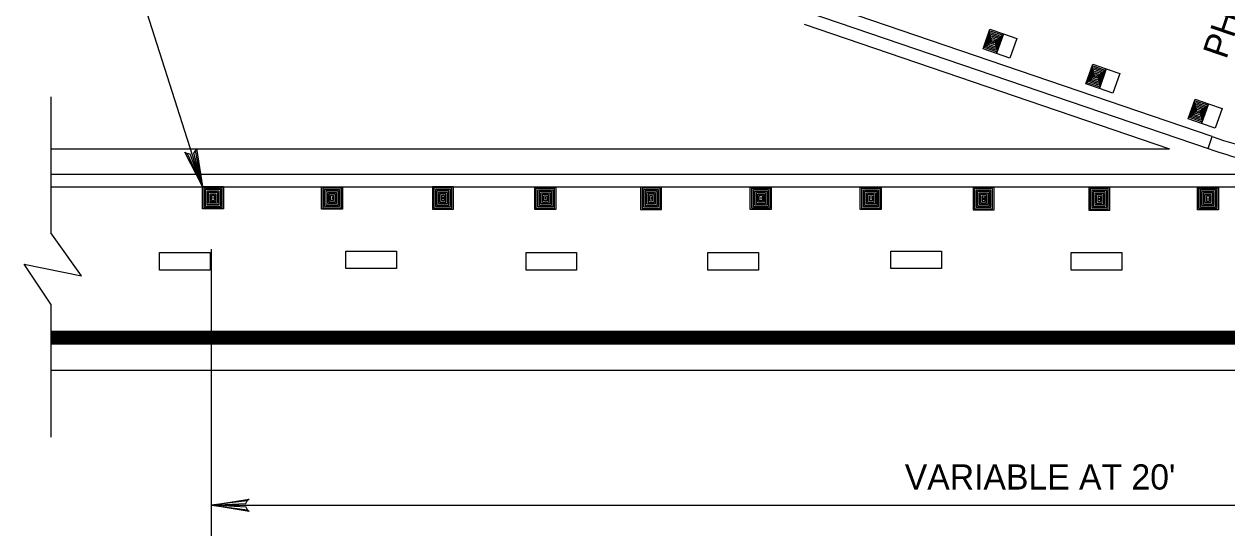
# Model space of a CAD drawing. Extents: x 639362 to 641108, y 298458 to 299646.
# Drawn here: x 639509.1 to 639652.3, y 299494 to 299554.9 of the extents above; entities that cross this region are included whole.
import ezdxf

# ---------------------------------------------------------------- set-up
doc = ezdxf.new("R2010")
doc.units = 0
doc.layers.add('2', color=7, linetype='Continuous')

msp = doc.modelspace()

# ---------------------------------------------------------------- linework, layer by layer
at = {"layer": '2'}
for p, q in [((639530.34, 299535.6), (639521.36, 299563.76)), ((639650.51, 299541.55), (639602.91, 299557.79)), ((639602.39, 299556.38), (639650.01, 299540.13)), ((639601.94, 299554.95), (639645.41, 299540.11)), ((639623.23, 299551.99), (639624.05, 299554.35)), ((639623.37, 299552.14), (639624.07, 299554.15)), ((639623.54, 299552.27), (639624.12, 299553.95)), ((639623.7, 299552.4), (639624.17, 299553.74)), ((639623.87, 299552.53), (639624.22, 299553.54)), ((639624.03, 299552.66), (639624.27, 299553.33)), ((639624.05, 299554.35), (639625.65, 299553.8)), ((639624.07, 299554.15), (639625.52, 299553.65)), ((639624.12, 299553.95), (639625.35, 299553.52)), ((639624.17, 299553.74), (639625.19, 299553.39)), ((639624.22, 299553.54), (639625.02, 299553.26)), ((639624.27, 299553.33), (639624.85, 299553.13)), ((639625.02, 299553.26), (639624.67, 299552.25)), ((639625.19, 299553.39), (639624.72, 299552.05)), ((639625.35, 299553.52), (639624.77, 299551.84)), ((639625.52, 299553.65), (639624.82, 299551.64)), ((639625.65, 299553.8), (639624.83, 299551.43)), ((639624.83, 299551.43), (639623.23, 299551.99)), ((639624.82, 299551.64), (639623.37, 299552.14)), ((639624.77, 299551.84), (639623.54, 299552.27)), ((639624.72, 299552.05), (639623.7, 299552.4)), ((639624.67, 299552.25), (639623.87, 299552.53)), ((639624.62, 299552.46), (639624.03, 299552.66)), ((639624.2, 299552.79), (639624.31, 299553.13)), ((639624.57, 299552.66), (639624.2, 299552.79)), ((639624.31, 299553.13), (639624.69, 299553)), ((639624.36, 299552.92), (639624.52, 299552.86)), ((639624.69, 299553), (639624.57, 299552.66)), ((639624.85, 299553.13), (639624.62, 299552.46)), ((639635.47, 299547.82), (639636.29, 299550.18)), ((639635.61, 299547.96), (639636.31, 299549.98)), ((639635.78, 299548.1), (639636.36, 299549.77)), ((639635.95, 299548.23), (639636.41, 299549.57)), ((639636.11, 299548.36), (639636.46, 299549.36)), ((639636.28, 299548.49), (639636.51, 299549.16)), ((639636.29, 299550.18), (639637.9, 299549.62)), ((639636.31, 299549.98), (639637.76, 299549.47)), ((639636.36, 299549.77), (639637.6, 299549.35)), ((639636.41, 299549.57), (639637.43, 299549.21)), ((639636.44, 299548.62), (639636.56, 299548.95)), ((639636.46, 299549.36), (639637.26, 299549.09)), ((639636.51, 299549.16), (639637.1, 299548.95)), ((639636.56, 299548.95), (639636.93, 299548.82)), ((639637.1, 299548.95), (639636.87, 299548.28)), ((639637.26, 299549.09), (639636.92, 299548.08)), ((639637.43, 299549.21), (639636.96, 299547.87)), ((639637.6, 299549.35), (639637.01, 299547.67)), ((639637.76, 299549.47), (639637.06, 299547.46)), ((639637.9, 299549.62), (639637.08, 299547.26)), ((639637.08, 299547.26), (639635.47, 299547.82)), ((639637.06, 299547.46), (639635.61, 299547.96)), ((639637.01, 299547.67), (639635.78, 299548.1)), ((639636.96, 299547.87), (639635.95, 299548.23)), ((639636.92, 299548.08), (639636.11, 299548.36)), ((639636.87, 299548.28), (639636.28, 299548.49)), ((639636.82, 299548.49), (639636.44, 299548.62)), ((639636.61, 299548.75), (639636.77, 299548.69)), ((639636.93, 299548.82), (639636.82, 299548.49)), ((639512.29, 299546.29), (639512.29, 299530.08)), ((639647.65, 299543.66), (639648.47, 299546.02)), ((639647.79, 299543.81), (639648.49, 299545.82)), ((639647.96, 299543.94), (639648.54, 299545.62)), ((639648.12, 299544.07), (639648.59, 299545.41)), ((639648.29, 299544.2), (639648.64, 299545.21)), ((639648.45, 299544.33), (639648.68, 299545)), ((639648.47, 299546.02), (639650.07, 299545.47)), ((639648.49, 299545.82), (639649.94, 299545.32)), ((639648.54, 299545.62), (639649.77, 299545.19)), ((639648.59, 299545.41), (639649.61, 299545.06)), ((639648.62, 299544.46), (639648.73, 299544.8)), ((639648.64, 299545.21), (639649.44, 299544.93)), ((639648.68, 299545), (639649.27, 299544.8)), ((639648.73, 299544.8), (639649.11, 299544.67)), ((639649.11, 299544.67), (639648.99, 299544.33)), ((639649.27, 299544.8), (639649.04, 299544.13)), ((639649.44, 299544.93), (639649.09, 299543.92)), ((639649.61, 299545.06), (639649.14, 299543.72)), ((639649.77, 299545.19), (639649.19, 299543.51)), ((639649.94, 299545.32), (639649.24, 299543.31)), ((639650.07, 299545.47), (639649.25, 299543.1)), ((639649.25, 299543.1), (639647.65, 299543.66)), ((639649.24, 299543.31), (639647.79, 299543.81)), ((639649.19, 299543.51), (639647.96, 299543.94)), ((639649.14, 299543.72), (639648.12, 299544.07)), ((639649.09, 299543.92), (639648.29, 299544.2)), ((639649.04, 299544.13), (639648.45, 299544.33)), ((639648.99, 299544.33), (639648.62, 299544.46)), ((639648.78, 299544.59), (639648.94, 299544.53)), ((639650.01, 299540.13), (639650.51, 299541.55)), ((639512.29, 299540.11), (639645.41, 299540.11)), ((639512.29, 299537.09), (639661.38, 299537.09)), ((639512.29, 299535.59), (639737.89, 299535.59)), ((639530.34, 299535.6), (639532.84, 299535.6)), ((639530.34, 299532.95), (639530.34, 299535.6)), ((639530.53, 299535.47), (639532.65, 299535.47)), ((639530.53, 299533.08), (639530.53, 299535.47)), ((639530.7, 299535.29), (639532.48, 299535.29)), ((639530.7, 299533.25), (639530.7, 299535.29)), ((639530.88, 299535.11), (639532.3, 299535.11)), ((639530.88, 299533.43), (639530.88, 299535.11)), ((639531.06, 299534.94), (639532.12, 299534.94)), ((639531.06, 299533.61), (639531.06, 299534.94)), ((639531.24, 299533.79), (639531.24, 299534.76)), ((639531.24, 299534.76), (639531.95, 299534.76)), ((639531.95, 299534.76), (639531.95, 299533.79)), ((639532.12, 299534.94), (639532.12, 299533.61)), ((639532.3, 299535.11), (639532.3, 299533.43)), ((639532.48, 299535.29), (639532.48, 299533.25)), ((639532.65, 299535.47), (639532.65, 299533.08)), ((639532.84, 299535.6), (639532.84, 299532.95)), ((639544.52, 299535.57), (639547.01, 299535.57)), ((639544.52, 299532.92), (639544.52, 299535.57)), ((639544.7, 299535.44), (639546.83, 299535.44)), ((639544.7, 299533.05), (639544.7, 299535.44)), ((639544.88, 299535.26), (639546.66, 299535.26)), ((639544.88, 299533.22), (639544.88, 299535.26)), ((639545.06, 299535.08), (639546.48, 299535.08)), ((639545.06, 299533.4), (639545.06, 299535.08)), ((639545.24, 299534.91), (639546.3, 299534.91)), ((639545.24, 299533.58), (639545.24, 299534.91)), ((639545.41, 299533.76), (639545.41, 299534.73)), ((639545.41, 299534.73), (639546.12, 299534.73)), ((639546.12, 299534.73), (639546.12, 299533.76)), ((639546.3, 299534.91), (639546.3, 299533.58)), ((639546.48, 299535.08), (639546.48, 299533.4)), ((639546.66, 299535.26), (639546.66, 299533.22)), ((639546.83, 299535.44), (639546.83, 299533.05)), ((639547.01, 299535.57), (639547.01, 299532.92)), ((639560.21, 299535.57), (639557.71, 299535.57)), ((639557.71, 299535.57), (639557.71, 299532.92)), ((639560.02, 299535.44), (639557.89, 299535.44)), ((639557.89, 299535.44), (639557.89, 299533.05)), ((639559.84, 299535.26), (639558.07, 299535.26)), ((639558.07, 299535.26), (639558.07, 299533.22)), ((639559.67, 299535.08), (639558.25, 299535.08)), ((639558.25, 299535.08), (639558.25, 299533.4)), ((639559.49, 299534.91), (639558.43, 299534.91)), ((639558.43, 299534.91), (639558.43, 299533.58)), ((639558.6, 299534.73), (639558.6, 299533.76)), ((639559.31, 299534.73), (639558.6, 299534.73)), ((639559.31, 299533.76), (639559.31, 299534.73)), ((639559.49, 299533.58), (639559.49, 299534.91)), ((639559.67, 299533.4), (639559.67, 299535.08)), ((639559.84, 299533.22), (639559.84, 299535.26)), ((639560.02, 299533.05), (639560.02, 299535.44)), ((639560.21, 299532.92), (639560.21, 299535.57)), ((639569.89, 299535.54), (639572.39, 299535.54)), ((639569.89, 299532.89), (639569.89, 299535.54)), ((639570.07, 299535.41), (639572.2, 299535.41)), ((639570.07, 299533.01), (639570.07, 299535.41)), ((639570.25, 299535.23), (639572.03, 299535.23)), ((639570.25, 299533.19), (639570.25, 299535.23)), ((639570.43, 299535.05), (639571.85, 299535.05)), ((639570.43, 299533.37), (639570.43, 299535.05)), ((639570.61, 299534.87), (639571.67, 299534.87)), ((639570.61, 299533.55), (639570.61, 299534.87)), ((639570.79, 299533.72), (639570.79, 299534.7)), ((639570.79, 299534.7), (639571.49, 299534.7)), ((639571.49, 299534.7), (639571.49, 299533.72)), ((639571.67, 299534.87), (639571.67, 299533.55)), ((639571.85, 299535.05), (639571.85, 299533.37)), ((639572.03, 299535.23), (639572.03, 299533.19)), ((639572.2, 299535.41), (639572.2, 299533.01)), ((639572.39, 299535.54), (639572.39, 299532.89)), ((639584.98, 299535.53), (639582.48, 299535.53)), ((639582.48, 299535.53), (639582.48, 299532.88)), ((639584.8, 299535.4), (639582.67, 299535.4)), ((639582.67, 299535.4), (639582.67, 299533)), ((639584.62, 299535.22), (639582.84, 299535.22)), ((639582.84, 299535.22), (639582.84, 299533.18)), ((639584.44, 299535.04), (639583.02, 299535.04)), ((639583.02, 299535.04), (639583.02, 299533.36)), ((639584.26, 299534.86), (639583.2, 299534.86)), ((639583.2, 299534.86), (639583.2, 299533.54)), ((639583.38, 299534.69), (639583.38, 299533.71)), ((639584.09, 299534.69), (639583.38, 299534.69)), ((639584.09, 299533.71), (639584.09, 299534.69)), ((639584.26, 299533.54), (639584.26, 299534.86)), ((639584.44, 299533.36), (639584.44, 299535.04)), ((639584.62, 299533.18), (639584.62, 299535.22)), ((639584.8, 299533), (639584.8, 299535.4)), ((639584.98, 299532.88), (639584.98, 299535.53)), ((639595.54, 299535.55), (639598.03, 299535.55)), ((639595.54, 299532.89), (639595.54, 299535.55)), ((639595.72, 299535.41), (639597.85, 299535.41)), ((639595.72, 299533.02), (639595.72, 299535.41)), ((639595.9, 299535.24), (639597.68, 299535.24)), ((639595.9, 299533.2), (639595.9, 299535.24)), ((639596.08, 299535.06), (639597.5, 299535.06)), ((639596.08, 299533.38), (639596.08, 299535.06)), ((639596.26, 299534.88), (639597.32, 299534.88)), ((639596.26, 299533.55), (639596.26, 299534.88)), ((639596.44, 299533.73), (639596.44, 299534.71)), ((639596.44, 299534.71), (639597.14, 299534.71)), ((639597.14, 299534.71), (639597.14, 299533.73)), ((639597.32, 299534.88), (639597.32, 299533.55)), ((639597.5, 299535.06), (639597.5, 299533.38)), ((639597.68, 299535.24), (639597.68, 299533.2)), ((639597.85, 299535.41), (639597.85, 299533.02)), ((639598.03, 299535.55), (639598.03, 299532.89)), ((639608.63, 299535.53), (639611.13, 299535.53)), ((639608.63, 299532.88), (639608.63, 299535.53)), ((639608.82, 299535.4), (639610.95, 299535.4)), ((639608.82, 299533.01), (639608.82, 299535.4)), ((639609, 299535.22), (639610.77, 299535.22)), ((639609, 299533.19), (639609, 299535.22)), ((639609.17, 299535.05), (639610.59, 299535.05)), ((639609.17, 299533.36), (639609.17, 299535.05)), ((639609.35, 299534.87), (639610.42, 299534.87)), ((639609.35, 299533.54), (639609.35, 299534.87)), ((639609.53, 299533.72), (639609.53, 299534.69)), ((639609.53, 299534.69), (639610.24, 299534.69)), ((639610.24, 299534.69), (639610.24, 299533.72)), ((639610.42, 299534.87), (639610.42, 299533.54)), ((639610.59, 299535.05), (639610.59, 299533.36)), ((639610.77, 299535.22), (639610.77, 299533.19)), ((639610.95, 299535.4), (639610.95, 299533.01)), ((639611.13, 299535.53), (639611.13, 299532.88)), ((639624.55, 299535.5), (639622.05, 299535.5)), ((639622.05, 299535.5), (639622.05, 299532.84)), ((639624.36, 299535.36), (639622.23, 299535.36)), ((639622.23, 299535.36), (639622.23, 299532.97)), ((639624.18, 299535.19), (639622.41, 299535.19)), ((639622.41, 299535.19), (639622.41, 299533.15)), ((639624.01, 299535.01), (639622.59, 299535.01)), ((639622.59, 299535.01), (639622.59, 299533.32)), ((639623.83, 299534.83), (639622.76, 299534.83)), ((639622.76, 299534.83), (639622.76, 299533.5)), ((639622.94, 299534.65), (639622.94, 299533.68)), ((639623.65, 299534.65), (639622.94, 299534.65)), ((639623.65, 299533.68), (639623.65, 299534.65)), ((639623.83, 299533.5), (639623.83, 299534.83)), ((639624.01, 299533.32), (639624.01, 299535.01)), ((639624.18, 299533.15), (639624.18, 299535.19)), ((639624.36, 299532.97), (639624.36, 299535.36)), ((639624.55, 299532.84), (639624.55, 299535.5)), ((639638.31, 299535.45), (639635.82, 299535.45)), ((639635.82, 299535.45), (639635.82, 299532.8)), ((639638.13, 299535.32), (639636, 299535.32)), ((639636, 299535.32), (639636, 299532.93)), ((639637.95, 299535.14), (639636.17, 299535.14)), ((639636.17, 299535.14), (639636.17, 299533.11)), ((639637.77, 299534.97), (639636.35, 299534.97)), ((639636.35, 299534.97), (639636.35, 299533.28)), ((639637.6, 299534.79), (639636.53, 299534.79)), ((639636.53, 299534.79), (639636.53, 299533.46)), ((639636.71, 299534.61), (639636.71, 299533.64)), ((639637.42, 299534.61), (639636.71, 299534.61)), ((639637.42, 299533.64), (639637.42, 299534.61)), ((639637.6, 299533.46), (639637.6, 299534.79)), ((639637.77, 299533.28), (639637.77, 299534.97)), ((639637.95, 299533.11), (639637.95, 299535.14)), ((639638.13, 299532.93), (639638.13, 299535.32)), ((639638.31, 299532.8), (639638.31, 299535.45)), ((639648.74, 299535.51), (639651.24, 299535.51)), ((639648.74, 299532.85), (639648.74, 299535.51)), ((639648.93, 299535.37), (639651.06, 299535.37)), ((639648.93, 299532.98), (639648.93, 299535.37)), ((639649.11, 299535.2), (639650.88, 299535.2)), ((639649.11, 299533.16), (639649.11, 299535.2)), ((639649.28, 299535.02), (639650.7, 299535.02)), ((639649.28, 299533.34), (639649.28, 299535.02)), ((639649.46, 299534.84), (639650.53, 299534.84)), ((639649.46, 299533.51), (639649.46, 299534.84)), ((639649.64, 299533.69), (639649.64, 299534.67)), ((639649.64, 299534.67), (639650.35, 299534.67)), ((639650.35, 299534.67), (639650.35, 299533.69)), ((639650.53, 299534.84), (639650.53, 299533.51)), ((639650.7, 299535.02), (639650.7, 299533.34)), ((639650.88, 299535.2), (639650.88, 299533.16)), ((639651.06, 299535.37), (639651.06, 299532.98)), ((639651.24, 299535.51), (639651.24, 299532.85)), ((639532.48, 299533.25), (639530.7, 299533.25)), ((639532.3, 299533.43), (639530.88, 299533.43)), ((639532.12, 299533.61), (639531.06, 299533.61)), ((639531.95, 299533.79), (639531.24, 299533.79)), ((639531.42, 299534.58), (639531.77, 299534.58)), ((639531.42, 299533.96), (639531.42, 299534.58)), ((639531.77, 299533.96), (639531.42, 299533.96)), ((639531.59, 299534.41), (639531.59, 299534.14)), ((639531.77, 299534.58), (639531.77, 299533.96)), ((639546.66, 299533.22), (639544.88, 299533.22)), ((639546.48, 299533.4), (639545.06, 299533.4)), ((639546.3, 299533.58), (639545.24, 299533.58)), ((639546.12, 299533.76), (639545.41, 299533.76)), ((639545.59, 299534.56), (639545.94, 299534.56)), ((639545.59, 299533.93), (639545.59, 299534.56)), ((639545.94, 299533.93), (639545.59, 299533.93)), ((639545.76, 299534.38), (639545.76, 299534.11)), ((639545.94, 299534.56), (639545.94, 299533.93)), ((639558.07, 299533.22), (639559.84, 299533.22)), ((639558.25, 299533.4), (639559.67, 299533.4)), ((639558.43, 299533.58), (639559.49, 299533.58)), ((639558.6, 299533.76), (639559.31, 299533.76)), ((639559.13, 299534.56), (639558.78, 299534.56)), ((639558.78, 299534.56), (639558.78, 299533.93)), ((639558.78, 299533.93), (639559.13, 299533.93)), ((639558.96, 299534.38), (639558.96, 299534.11)), ((639559.13, 299533.93), (639559.13, 299534.56)), ((639572.03, 299533.19), (639570.25, 299533.19)), ((639571.85, 299533.37), (639570.43, 299533.37)), ((639571.67, 299533.55), (639570.61, 299533.55)), ((639571.49, 299533.72), (639570.79, 299533.72)), ((639570.96, 299534.52), (639571.32, 299534.52)), ((639570.96, 299533.9), (639570.96, 299534.52)), ((639571.32, 299533.9), (639570.96, 299533.9)), ((639571.14, 299534.34), (639571.14, 299534.08)), ((639571.32, 299534.52), (639571.32, 299533.9)), ((639582.84, 299533.18), (639584.62, 299533.18)), ((639583.02, 299533.36), (639584.44, 299533.36)), ((639583.2, 299533.54), (639584.26, 299533.54)), ((639583.38, 299533.71), (639584.09, 299533.71)), ((639583.91, 299534.51), (639583.55, 299534.51)), ((639583.55, 299534.51), (639583.55, 299533.89)), ((639583.55, 299533.89), (639583.91, 299533.89)), ((639583.73, 299534.33), (639583.73, 299534.07)), ((639583.91, 299533.89), (639583.91, 299534.51)), ((639597.68, 299533.2), (639595.9, 299533.2)), ((639597.5, 299533.38), (639596.08, 299533.38)), ((639597.32, 299533.55), (639596.26, 299533.55)), ((639597.14, 299533.73), (639596.44, 299533.73)), ((639596.61, 299534.53), (639596.97, 299534.53)), ((639596.61, 299533.91), (639596.61, 299534.53)), ((639596.97, 299533.91), (639596.61, 299533.91)), ((639596.79, 299534.35), (639596.79, 299534.08)), ((639596.97, 299534.53), (639596.97, 299533.91)), ((639610.77, 299533.19), (639609, 299533.19)), ((639610.59, 299533.36), (639609.17, 299533.36)), ((639610.42, 299533.54), (639609.35, 299533.54)), ((639610.24, 299533.72), (639609.53, 299533.72)), ((639609.71, 299534.52), (639610.06, 299534.52)), ((639609.71, 299533.89), (639609.71, 299534.52)), ((639610.06, 299533.89), (639609.71, 299533.89)), ((639609.88, 299534.34), (639609.88, 299534.07)), ((639610.06, 299534.52), (639610.06, 299533.89)), ((639622.59, 299533.32), (639624.01, 299533.32)), ((639622.76, 299533.5), (639623.83, 299533.5)), ((639622.94, 299533.68), (639623.65, 299533.68)), ((639623.47, 299534.48), (639623.12, 299534.48)), ((639623.12, 299534.48), (639623.12, 299533.86)), ((639623.12, 299533.86), (639623.47, 299533.86)), ((639623.3, 299534.3), (639623.3, 299534.03)), ((639623.47, 299533.86), (639623.47, 299534.48)), ((639636.35, 299533.28), (639637.77, 299533.28)), ((639636.53, 299533.46), (639637.6, 299533.46)), ((639636.71, 299533.64), (639637.42, 299533.64)), ((639637.24, 299534.44), (639636.89, 299534.44)), ((639636.89, 299534.44), (639636.89, 299533.81)), ((639636.89, 299533.81), (639637.24, 299533.81)), ((639637.06, 299534.26), (639637.06, 299533.99)), ((639637.24, 299533.81), (639637.24, 299534.44)), ((639650.88, 299533.16), (639649.11, 299533.16)), ((639650.7, 299533.34), (639649.28, 299533.34)), ((639650.53, 299533.51), (639649.46, 299533.51)), ((639650.35, 299533.69), (639649.64, 299533.69)), ((639649.82, 299534.49), (639650.17, 299534.49)), ((639649.82, 299533.87), (639649.82, 299534.49)), ((639650.17, 299533.87), (639649.82, 299533.87)), ((639649.99, 299534.31), (639649.99, 299534.04)), ((639650.17, 299534.49), (639650.17, 299533.87)), ((639532.84, 299532.95), (639530.34, 299532.95)), ((639532.65, 299533.08), (639530.53, 299533.08)), ((639547.01, 299532.92), (639544.52, 299532.92)), ((639546.83, 299533.05), (639544.7, 299533.05)), ((639557.71, 299532.92), (639560.21, 299532.92)), ((639557.89, 299533.05), (639560.02, 299533.05)), ((639572.39, 299532.89), (639569.89, 299532.89)), ((639572.2, 299533.01), (639570.07, 299533.01)), ((639582.48, 299532.88), (639584.98, 299532.88)), ((639582.67, 299533), (639584.8, 299533)), ((639598.03, 299532.89), (639595.54, 299532.89)), ((639597.85, 299533.02), (639595.72, 299533.02)), ((639611.13, 299532.88), (639608.63, 299532.88)), ((639610.95, 299533.01), (639608.82, 299533.01)), ((639622.05, 299532.84), (639624.55, 299532.84)), ((639622.23, 299532.97), (639624.36, 299532.97)), ((639622.41, 299533.15), (639624.18, 299533.15)), ((639635.82, 299532.8), (639638.31, 299532.8)), ((639636, 299532.93), (639638.13, 299532.93)), ((639636.17, 299533.11), (639637.95, 299533.11)), ((639651.24, 299532.85), (639648.74, 299532.85)), ((639651.06, 299532.98), (639648.93, 299532.98)), ((639515.93, 299524.97), (639512.29, 299530.08)), ((639525.22, 299525.67), (639525.22, 299527.74)), ((639525.22, 299527.74), (639531.24, 299527.74)), ((639531.24, 299527.74), (639531.24, 299525.67)), ((639531.37, 299528.16), (639531.37, 299494.02)), ((639547.41, 299525.86), (639547.41, 299527.93)), ((639547.41, 299527.93), (639553.43, 299527.93)), ((639553.43, 299527.93), (639553.43, 299525.86)), ((639568.86, 299525.67), (639568.86, 299527.74)), ((639568.86, 299527.74), (639574.87, 299527.74)), ((639574.87, 299527.74), (639574.87, 299525.67)), ((639590.49, 299525.67), (639590.49, 299527.74)), ((639590.49, 299527.74), (639596.5, 299527.74)), ((639596.5, 299527.74), (639596.5, 299525.67)), ((639612.27, 299525.86), (639612.27, 299527.93)), ((639612.27, 299527.93), (639618.29, 299527.93)), ((639618.29, 299527.93), (639618.29, 299525.86)), ((639633.73, 299525.67), (639633.73, 299527.74)), ((639633.73, 299527.74), (639639.74, 299527.74)), ((639639.74, 299527.74), (639639.74, 299525.67)), ((639512.29, 299521.6), (639509.11, 299526.37)), ((639509.11, 299526.37), (639515.93, 299524.97)), ((639531.24, 299525.67), (639525.22, 299525.67)), ((639553.43, 299525.86), (639547.41, 299525.86)), ((639574.87, 299525.67), (639568.86, 299525.67)), ((639596.5, 299525.67), (639590.49, 299525.67)), ((639618.29, 299525.86), (639612.27, 299525.86)), ((639639.74, 299525.67), (639633.73, 299525.67)), ((639512.29, 299521.6), (639512.29, 299505.78)), ((639512.29, 299518.38), (639813.29, 299518.38)), ((639512.29, 299518.23), (639813.29, 299518.23)), ((639512.29, 299518.08), (639813.29, 299518.08)), ((639512.29, 299517.93), (639813.29, 299517.93)), ((639512.29, 299517.78), (639813.29, 299517.78)), ((639512.29, 299517.63), (639813.29, 299517.63)), ((639512.29, 299517.48), (639813.29, 299517.48)), ((639512.29, 299517.33), (639813.29, 299517.33)), ((639512.29, 299517.18), (639813.29, 299517.18)), ((639512.29, 299517.03), (639813.29, 299517.03)), ((639512.29, 299516.88), (639813.29, 299516.88)), ((639512.29, 299513.74), (639813.29, 299513.74)), ((639531.37, 299497.67), (639734.72, 299497.67))]:
    msp.add_line(p, q, dxfattribs=at)
for points in [[(639624.83, 299551.43), (639625.65, 299553.8), (639627.26, 299553.24), (639626.44, 299550.88)], [(639637.08, 299547.26), (639637.9, 299549.62), (639639.5, 299549.07), (639638.68, 299546.71)], [(639649.25, 299543.1), (639650.07, 299545.47), (639651.68, 299544.91), (639650.86, 299542.55)]]:
    msp.add_lwpolyline(points, close=True, dxfattribs=at)
for points in [[(639529.52, 299539.88), (639529.27, 299539.63), (639530.34, 299535.6), (639529.52, 299539.88), (639529.63, 299540.14), (639530.34, 299535.6), (639528.86, 299539.48), (639528.52, 299539.54), (639530.34, 299535.6), (639528.25, 299539.69), (639528.52, 299539.54)], [(639535.69, 299497.12), (639535.53, 299497.44), (639531.37, 299497.67), (639535.69, 299497.12), (639535.91, 299496.93), (639531.37, 299497.67), (639535.52, 299497.87), (639535.67, 299498.18), (639531.37, 299497.67), (639535.91, 299498.39), (639535.67, 299498.18)]]:
    msp.add_lwpolyline(points, dxfattribs=at)
for centre, radius, start, end in [((639679.6, 299628.88), 92.05, 251.5767, 265.7693), ((639680.87, 299632.65), 97.53, 251.5563, 258.4732)]:
    msp.add_arc(centre, radius, start, end, dxfattribs=at)

# ---------------------------------------------------------------- texts
msp.add_text('PHYSICAL', height=3, rotation=71.1572, dxfattribs=at).set_placement((639652.17, 299550.66))
msp.add_text("VARIABLE AT 20'", height=3, dxfattribs=at).set_placement((639613.92, 299499.54))

doc.saveas('drawing.dxf')
